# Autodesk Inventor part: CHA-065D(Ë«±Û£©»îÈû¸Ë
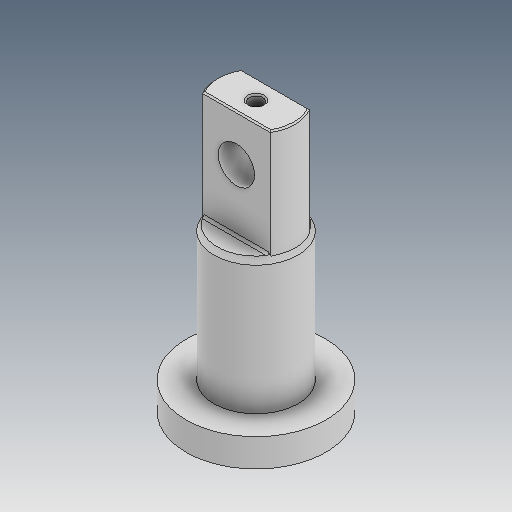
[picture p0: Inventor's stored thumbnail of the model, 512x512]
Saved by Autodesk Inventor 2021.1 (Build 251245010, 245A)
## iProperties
Created: 2019-12
Part Number: CHA-065D(Ë«±Û£©»îÈû¸Ë
Material: Ogólny
Document SubType Name: Modeling
Designer: user
Density: 1 g/cm^3
Appearance: Domyślna
Author: user
Revision Number: ÈÎºÎ
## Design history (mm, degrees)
feature "ÊäÈë1"
node "Bryła1"
